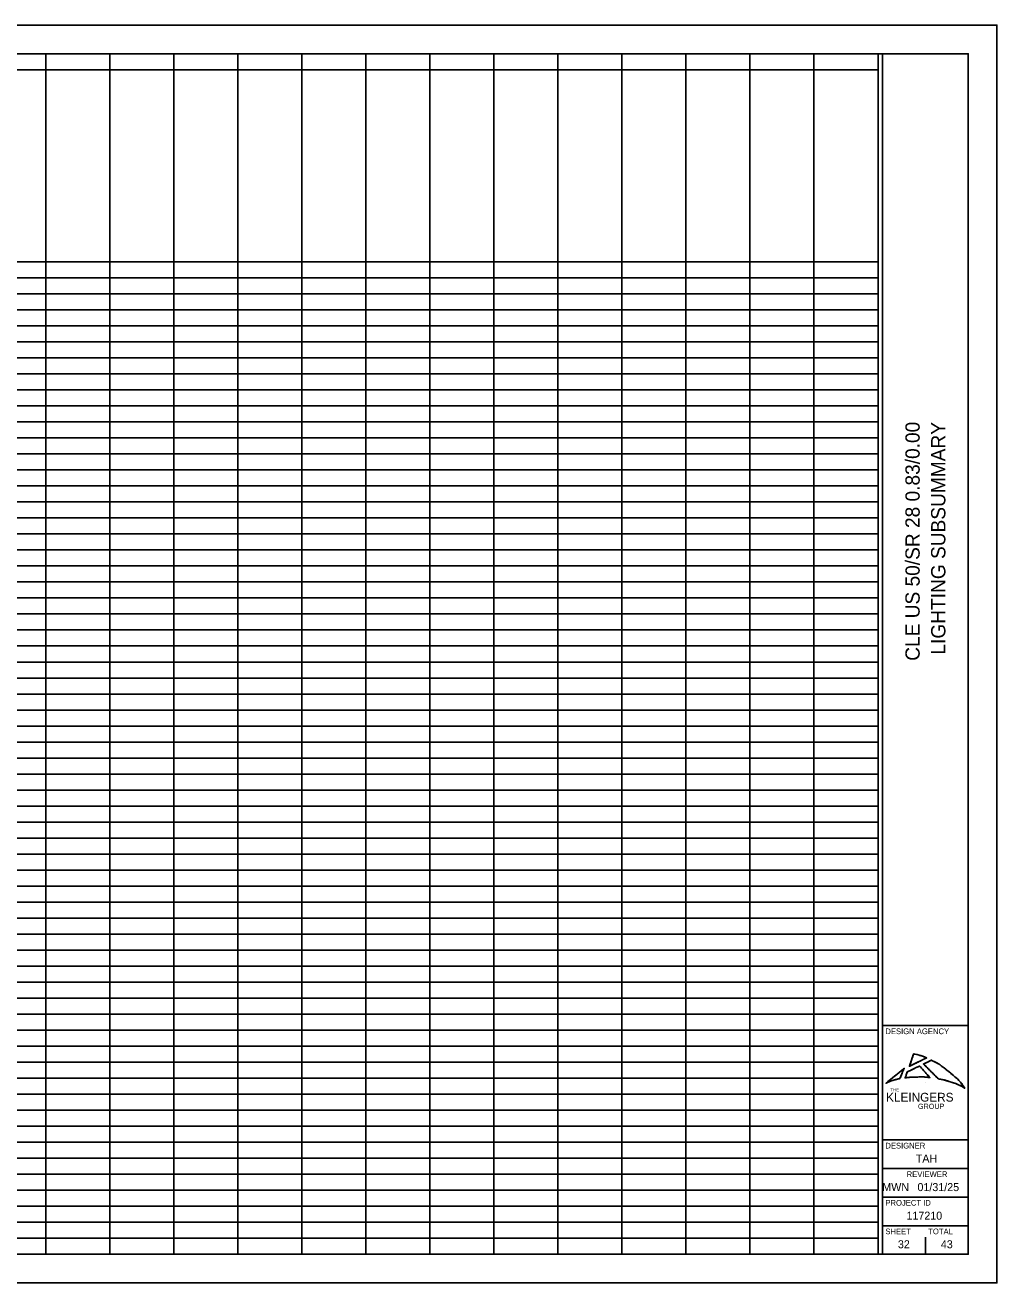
# Model space of a CAD drawing. Extents: x 0 to 34, y 0 to 22.
# Drawn here: x 17 to 34, y 0 to 22 of the extents above; entities that cross this region are included whole.
import ezdxf

# ---------------------------------------------------------------- set-up
doc = ezdxf.new("R2010")
doc.units = 0
for name, color, linetype in [('SH_Border', 7, 'Continuous'), ('SH_Cut_Line', 7, 'Continuous'), ('SH_Data', 7, 'Continuous'), ('SH_Text', 7, 'Continuous')]:
    doc.layers.add(name, color=color, linetype=linetype)

msp = doc.modelspace()

# ---------------------------------------------------------------- linework, layer by layer
at = {"layer": 'SH_Border'}
for p, q in [((32, 0.5), (32, 21.5)), ((32, 4.5), (33.5, 4.5)), ((32, 2.5), (33.5, 2.5)), ((32, 2), (33.5, 2)), ((32, 1.5), (33.5, 1.5)), ((32, 1), (33.5, 1))]:
    msp.add_line(p, q, dxfattribs=at)
msp.add_lwpolyline([(1.5, 21.5), (33.5, 21.5), (33.5, 0.5), (1.5, 0.5)], close=True, dxfattribs=at)
at = {"layer": 'SH_Cut_Line'}
msp.add_lwpolyline([(0, 0), (34, 0), (34, 22), (0, 22)], close=True, dxfattribs=at)
at = {"layer": 'SH_Data'}
for p, q in [((1.5, 21.5), (31.921, 21.5)), ((17.361, 21.5), (17.361, 0.5)), ((18.481, 21.5), (18.481, 0.5)), ((19.601, 21.5), (19.601, 0.5)), ((20.721, 21.5), (20.721, 0.5)), ((21.841, 21.5), (21.841, 0.5)), ((22.961, 21.5), (22.961, 0.5)), ((24.081, 21.5), (24.081, 0.5)), ((25.201, 21.5), (25.201, 0.5)), ((26.321, 21.5), (26.321, 0.5)), ((27.441, 21.5), (27.441, 0.5)), ((28.561, 21.5), (28.561, 0.5)), ((29.681, 21.5), (29.681, 0.5)), ((30.801, 21.5), (30.801, 0.5)), ((31.921, 21.5), (31.921, 0.5)), ((9.521, 21.22), (31.921, 21.22)), ((9.521, 17.86), (31.921, 17.86)), ((1.5, 17.58), (31.921, 17.58)), ((1.5, 17.3), (31.921, 17.3)), ((1.5, 17.02), (31.921, 17.02)), ((1.5, 16.74), (31.921, 16.74)), ((1.5, 16.46), (31.921, 16.46)), ((1.5, 16.18), (31.921, 16.18)), ((1.5, 15.9), (31.921, 15.9)), ((1.5, 15.62), (31.921, 15.62)), ((1.5, 15.34), (31.921, 15.34)), ((1.5, 15.06), (31.921, 15.06)), ((1.5, 14.78), (31.921, 14.78)), ((1.5, 14.5), (31.921, 14.5)), ((1.5, 14.22), (31.921, 14.22)), ((1.5, 13.94), (31.921, 13.94)), ((1.5, 13.66), (31.921, 13.66)), ((1.5, 13.38), (31.921, 13.38)), ((1.5, 13.1), (31.921, 13.1)), ((1.5, 12.82), (31.921, 12.82)), ((1.5, 12.54), (31.921, 12.54)), ((1.5, 12.26), (31.921, 12.26)), ((1.5, 11.98), (31.921, 11.98)), ((1.5, 11.7), (31.921, 11.7)), ((1.5, 11.42), (31.921, 11.42)), ((1.5, 11.14), (31.921, 11.14)), ((1.5, 10.86), (31.921, 10.86)), ((1.5, 10.58), (31.921, 10.58)), ((1.5, 10.3), (31.921, 10.3)), ((1.5, 10.02), (31.921, 10.02)), ((1.5, 9.74), (31.921, 9.74)), ((1.5, 9.46), (31.921, 9.46)), ((1.5, 9.18), (31.921, 9.18)), ((1.5, 8.9), (31.921, 8.9)), ((1.5, 8.62), (31.921, 8.62)), ((1.5, 8.34), (31.921, 8.34)), ((1.5, 8.06), (31.921, 8.06)), ((1.5, 7.78), (31.921, 7.78)), ((1.5, 7.5), (31.921, 7.5)), ((1.5, 7.22), (31.921, 7.22)), ((1.5, 6.94), (31.921, 6.94)), ((1.5, 6.66), (31.921, 6.66)), ((1.5, 6.38), (31.921, 6.38)), ((1.5, 6.1), (31.921, 6.1)), ((1.5, 5.82), (31.921, 5.82)), ((1.5, 5.54), (31.921, 5.54)), ((1.5, 5.26), (31.921, 5.26)), ((1.5, 4.98), (31.921, 4.98)), ((1.5, 4.7), (31.921, 4.7)), ((1.5, 4.42), (31.921, 4.42)), ((1.5, 4.14), (31.921, 4.14)), ((1.5, 3.86), (31.921, 3.86)), ((1.5, 3.58), (31.921, 3.58)), ((32.75, 3.5), (32.75, 3.5)), ((1.5, 3.3), (31.921, 3.3)), ((1.5, 3.02), (31.921, 3.02)), ((1.5, 2.74), (31.921, 2.74)), ((1.5, 2.46), (31.921, 2.46)), ((1.5, 2.18), (31.921, 2.18)), ((1.5, 1.9), (31.921, 1.9)), ((1.5, 1.62), (31.921, 1.62)), ((1.5, 1.34), (31.921, 1.34)), ((1.5, 1.06), (31.921, 1.06)), ((1.5, 0.78), (31.921, 0.78)), ((32.375, 0.675), (32.375, 0.675)), ((32.75, 0.5), (32.75, 0.8)), ((1.5, 0.5), (31.921, 0.5))]:
    msp.add_line(p, q, dxfattribs=at)
at = {"layer": 'SH_Text'}
for points, degree in [([(32.542, 4.004), (32.542, 4.004), (32.47, 3.788), (32.47, 3.788)], 2), ([(32.772, 3.935), (32.772, 3.935), (32.722, 3.959), (32.655, 3.979), (32.588, 3.999), (32.542, 4.004), (32.542, 4.004), (32.542, 4.004), (32.47, 3.788), (32.47, 3.788), (32.47, 3.788), (32.772, 3.935), (32.772, 3.935)], 3), ([(32.772, 3.935), (32.772, 3.935), (32.722, 3.959), (32.655, 3.979)], 2), ([(32.379, 3.752), (32.379, 3.752), (32.062, 3.492), (32.062, 3.492)], 2), ([(32.379, 3.752), (32.379, 3.752), (32.062, 3.492), (32.062, 3.492), (32.062, 3.492), (32.133, 3.529), (32.21, 3.55), (32.28, 3.569), (32.303, 3.572), (32.303, 3.572), (32.303, 3.572), (32.379, 3.752), (32.379, 3.752)], 3), ([(32.303, 3.572), (32.303, 3.572), (32.379, 3.752), (32.379, 3.752)], 2), ([(32.648, 3.793), (32.648, 3.793), (32.83, 3.589), (32.83, 3.589), (32.83, 3.589), (32.734, 3.604), (32.602, 3.6), (32.455, 3.596), (32.396, 3.584), (32.396, 3.584), (32.396, 3.584), (32.434, 3.691), (32.434, 3.691), (32.434, 3.691), (32.648, 3.793), (32.648, 3.793)], 3), ([(32.434, 3.691), (32.434, 3.691), (32.648, 3.793), (32.648, 3.793)], 2), ([(32.47, 3.788), (32.47, 3.788), (32.772, 3.935), (32.772, 3.935)], 2), ([(32.648, 3.793), (32.648, 3.793), (32.83, 3.589), (32.83, 3.589)], 2), ([(33.2, 3.512), (33.079, 3.551), (32.978, 3.567), (32.978, 3.567), (32.978, 3.567), (32.717, 3.827), (32.717, 3.827), (32.717, 3.827), (32.855, 3.894), (32.855, 3.894), (32.855, 3.894), (32.985, 3.834), (33.142, 3.708), (33.348, 3.542), (33.439, 3.405), (33.439, 3.405), (33.439, 3.405), (33.351, 3.463), (33.2, 3.512)], 3), ([(32.717, 3.827), (32.717, 3.827), (32.855, 3.894), (32.855, 3.894)], 2), ([(32.978, 3.567), (32.978, 3.567), (32.717, 3.827), (32.717, 3.827)], 2), ([(32.855, 3.894), (32.855, 3.894), (32.985, 3.834), (33.142, 3.708)], 2), ([(32.062, 3.492), (32.062, 3.492), (32.133, 3.529), (32.21, 3.55)], 2), ([(32.21, 3.55), (32.28, 3.569), (32.303, 3.572), (32.303, 3.572)], 2), ([(32.396, 3.584), (32.396, 3.584), (32.434, 3.691), (32.434, 3.691)], 2), ([(32.602, 3.6), (32.455, 3.596), (32.396, 3.584), (32.396, 3.584)], 2), ([(32.83, 3.589), (32.83, 3.589), (32.734, 3.604), (32.602, 3.6)], 2), ([(33.2, 3.512), (33.079, 3.551), (32.978, 3.567), (32.978, 3.567)], 2), ([(33.142, 3.708), (33.348, 3.542), (33.439, 3.405), (33.439, 3.405)], 2), ([(33.439, 3.405), (33.439, 3.405), (33.351, 3.463), (33.2, 3.512)], 2)]:
    msp.add_open_spline(points, degree=degree, dxfattribs=at)

# ---------------------------------------------------------------- texts
at = {"layer": 'SH_Data'}
for s, p in [('CLE US 50/SR 28 0.83/0.00', (32.65, 10.881)), ('LIGHTING SUBSUMMARY', (33.1, 10.99))]:
    msp.add_text(s, height=0.25, rotation=90, dxfattribs=at).set_placement(p)
for s, height, p in [('DESIGN AGENCY', 0.1, (32.05, 4.35)), ('DESIGNER', 0.1, (32.05, 2.35)), ('TAH', 0.14, (32.582, 2.105)), ('REVIEWER', 0.1, (32.422, 1.85)), ('MWN', 0.14, (31.996, 1.605)), ('01/31/25', 0.14, (32.611, 1.605)), ('PROJECT ID', 0.1, (32.05, 1.35)), ('117210', 0.14, (32.419, 1.105)), ('SHEET', 0.1, (32.05, 0.85)), ('TOTAL', 0.1, (32.8, 0.85)), ('32', 0.14, (32.269, 0.605)), ('43', 0.14, (33.02, 0.605))]:
    msp.add_text(s, height=height, dxfattribs=at).set_placement(p)
at = {"layer": 'SH_Text'}
for s, height, p in [('KLEINGERS', 0.1542, (32.062, 3.17)), ('THE', 0.0561, (32.135, 3.349)), ('GROUP', 0.0911, (32.62, 3.042))]:
    msp.add_text(s, height=height, dxfattribs=at).set_placement(p)

doc.saveas('drawing.dxf')
